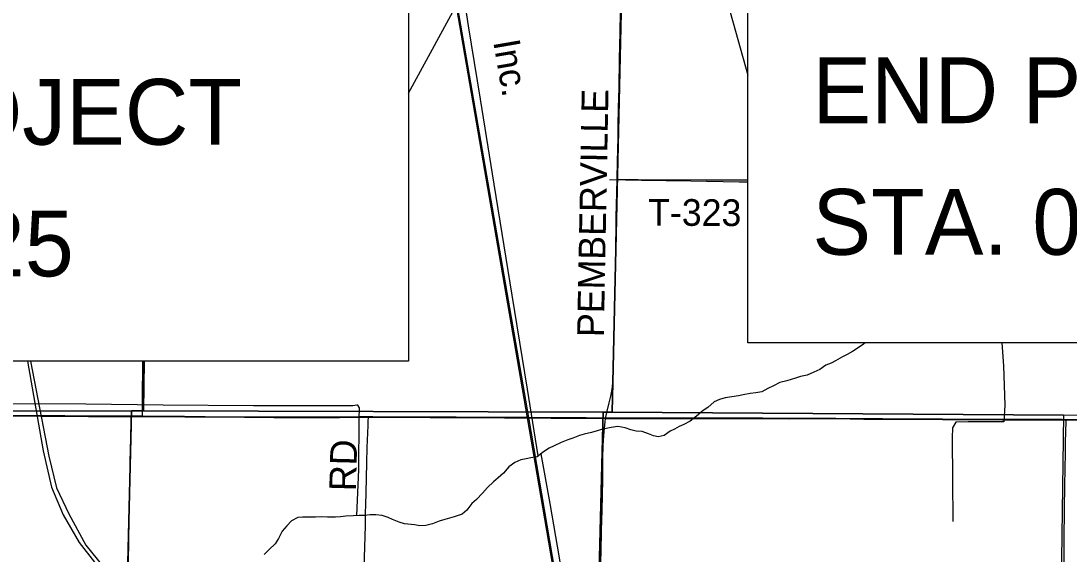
# Model space of a CAD drawing. Extents: x 0 to 34, y 0 to 22.
# Drawn here: x 4.218 to 6.448, y 15.733 to 16.867 of the extents above; entities that cross this region are included whole.
import ezdxf

# ---------------------------------------------------------------- set-up
doc = ezdxf.new("R2010")
doc.units = 0
for name, color, linetype in [('GM_X_County_Road', 7, 'Continuous'), ('GM_X_County_Road_Text', 7, 'Continuous'), ('GM_X_Minor_River', 7, 'Continuous'), ('GM_X_Rail_Line', 7, 'Continuous'), ('GM_X_Rail_Line_Text', 7, 'Continuous'), ('GM_X_Section', 7, 'Continuous'), ('GM_X_Township_Road', 7, 'Continuous'), ('GM_X_Township_Road_Text', 7, 'Continuous'), ('GM_X_US_Route', 7, 'Continuous'), ('SH_Text', 7, 'Continuous'), ('TX_P_1', 7, 'Continuous')]:
    doc.layers.add(name, color=color, linetype=linetype)

msp = doc.modelspace()

# ---------------------------------------------------------------- linework, layer by layer
at = {"layer": 'GM_X_County_Road'}
for p, q in [((4.4524, 16.0253), (4.4762, 16.0252)), ((6.4425, 16.0181), (6.4745, 16.0177))]:
    msp.add_line(p, q, dxfattribs=at)
for points in [[(5.4866, 16.5301), (5.4875, 16.5679), (5.4888, 16.6189), (5.4891, 16.6437), (5.4897, 16.6823), (5.4908, 16.7239), (5.492, 16.7867), (5.4931, 16.8433), (5.4937, 16.8855), (5.4939, 16.9067), (5.4945, 16.9576), (5.4946, 17.0204), (5.4947, 17.038)], [(5.4622, 16.0215), (5.4649, 16.0343), (5.4698, 16.0544), (5.4731, 16.0684), (5.4753, 16.0794), (5.4767, 16.0886), (5.4777, 16.0979), (5.4784, 16.1091), (5.4789, 16.1284), (5.4799, 16.1794), (5.4805, 16.2136), (5.4836, 16.3665), (5.4849, 16.4498), (5.486, 16.5014), (5.4866, 16.5301)], [(3.4764, 16.0302), (3.4941, 16.0299), (3.5158, 16.0296), (3.5842, 16.029), (3.6402, 16.0284), (3.7179, 16.028), (3.7552, 16.0278), (3.8018, 16.0277), (3.8671, 16.0272), (3.9075, 16.0272), (4.0038, 16.0267), (4.0287, 16.0268), (4.0753, 16.0265), (4.1406, 16.0266), (4.2618, 16.0262), (4.3115, 16.026), (4.3613, 16.0257), (4.4141, 16.0255), (4.4524, 16.0253)], [(4.4762, 16.0252), (4.4856, 16.0252), (4.5664, 16.0247), (4.6099, 16.0244), (4.6938, 16.0237), (4.756, 16.0236), (4.7995, 16.0235), (4.8959, 16.0236), (4.9363, 16.0239), (4.9572, 16.0239)], [(4.9572, 16.0239), (4.9674, 16.0239), (5.014, 16.0238), (5.0886, 16.0235), (5.1072, 16.0233), (5.1445, 16.0233), (5.2067, 16.023), (5.2471, 16.0227), (5.2689, 16.0226), (5.2906, 16.0226), (5.2999, 16.0225), (5.3279, 16.0223), (5.3465, 16.0222), (5.4211, 16.0218), (5.4622, 16.0215)], [(5.4507, 15.657), (5.4529, 15.7422), (5.4537, 15.7782), (5.4537, 15.7827), (5.4547, 15.8263), (5.4553, 15.8577), (5.4561, 15.8919), (5.4566, 15.937), (5.4572, 15.9634), (5.4586, 15.9849), (5.4597, 16.0004), (5.461, 16.0139), (5.4622, 16.0215)], [(5.4622, 16.0215), (5.4646, 16.0215), (5.4957, 16.0214), (5.5454, 16.0211), (5.6231, 16.0211), (5.6635, 16.0212), (5.7039, 16.0214), (5.7972, 16.0212), (5.8531, 16.0207), (5.8966, 16.0209), (5.9526, 16.0209), (6.0116, 16.02), (6.0521, 16.0199), (6.1795, 16.0194), (6.3069, 16.0183), (6.3473, 16.0183), (6.4343, 16.0182), (6.4425, 16.0181)]]:
    msp.add_lwpolyline(points, dxfattribs=at)
at = {"layer": 'GM_X_Minor_River'}
for points in [[(5.3189, 15.9417), (5.2959, 16.0838), (5.2634, 16.2838), (5.2253, 16.5197), (5.1957, 16.7006), (5.1705, 16.8565), (5.1572, 16.9463), (5.1426, 17.0309), (5.1183, 17.1951)], [(5.7647, 16.5241), (5.7462, 16.5241), (5.6436, 16.5262), (5.5387, 16.5272), (5.4706, 16.5289)], [(6.0148, 16.1819), (6.0107, 16.1796), (5.9998, 16.1715), (5.9875, 16.1638), (5.976, 16.1573), (5.966, 16.1522), (5.9514, 16.1438), (5.9419, 16.1391), (5.9308, 16.1345), (5.918, 16.1257), (5.905, 16.1195), (5.8909, 16.1134), (5.8768, 16.1107), (5.8661, 16.1068), (5.8478, 16.1016), (5.8329, 16.0977), (5.8195, 16.0905), (5.8076, 16.0851), (5.7946, 16.0782), (5.782, 16.0758), (5.7695, 16.0742), (5.7546, 16.0716), (5.7447, 16.0695), (5.731, 16.0676), (5.7166, 16.0653), (5.7044, 16.0614), (5.6929, 16.0564), (5.6794, 16.0449), (5.6697, 16.0383), (5.6558, 16.0261), (5.6423, 16.0155), (5.6288, 16.0086), (5.6185, 16.0039), (5.6089, 15.9988), (5.5993, 15.9941), (5.587, 15.9853), (5.574, 15.9822), (5.5639, 15.9843), (5.5534, 15.9888), (5.5399, 15.9933), (5.5274, 15.994), (5.5161, 15.9973), (5.5037, 16.0014), (5.4882, 16.004), (5.4738, 16.0021), (5.4635, 16.0001), (5.4536, 15.998), (5.4441, 15.9948)], [(6.3057, 16.1819), (6.3087, 16.1333), (6.3115, 16.0493), (6.3099, 16.0141), (6.2341, 16.014), (6.2072, 16.0135), (6.2005, 16.0012), (6.2, 15.9803), (6.2004, 15.8911), (6.2009, 15.8019)], [(4.9325, 15.8145), (4.9369, 15.913), (4.9376, 16.0208), (4.9386, 16.0439), (4.9346, 16.0493), (4.9327, 16.0494), (4.9239, 16.0484), (4.713, 16.0482), (4.5203, 16.0499), (4.356, 16.0519), (4.1897, 16.0525), (4.0765, 16.0504), (3.9632, 16.0504), (3.8496, 16.0498), (3.7334, 16.0503), (3.5781, 16.0499)], [(5.4441, 15.9948), (5.4323, 15.9913), (5.4166, 15.9875), (5.4063, 15.9847), (5.3922, 15.9794), (5.3819, 15.9759), (5.3673, 15.9701), (5.3524, 15.9633), (5.3424, 15.9582), (5.3298, 15.9506), (5.3166, 15.9399), (5.3029, 15.9375), (5.293, 15.9355), (5.2816, 15.9331), (5.2693, 15.9274), (5.2562, 15.9182), (5.2446, 15.9052), (5.2333, 15.8948), (5.2233, 15.8867), (5.2108, 15.8745), (5.1999, 15.8626), (5.1875, 15.8489), (5.1778, 15.84), (5.1669, 15.8262), (5.1568, 15.8177), (5.1396, 15.8117), (5.1202, 15.8061), (5.108, 15.8026), (5.0934, 15.7969), (5.0797, 15.7934), (5.0668, 15.7926), (5.0555, 15.7948), (5.0343, 15.7968), (5.0231, 15.8009), (5.0088, 15.8062), (4.9991, 15.8106), (4.9863, 15.8147), (4.9731, 15.8165), (4.9614, 15.8164), (4.9492, 15.8148), (4.9375, 15.8147), (4.925, 15.8143), (4.909, 15.8131), (4.8976, 15.8119), (4.8874, 15.8114), (4.87, 15.811), (4.8575, 15.8117), (4.845, 15.8116), (4.8317, 15.8116), (4.8173, 15.8116), (4.8071, 15.8107), (4.794, 15.8038), (4.7835, 15.7926), (4.7738, 15.7815), (4.7662, 15.7657), (4.7591, 15.7545), (4.7463, 15.7423), (4.7354, 15.7316)], [(5.3241, 15.946), (5.3437, 15.8402), (5.3635, 15.7247), (5.3849, 15.5925)]]:
    msp.add_lwpolyline(points, dxfattribs=at)
at = {"layer": 'GM_X_Rail_Line'}
for points in [[(5.5292, 14.4768), (5.5206, 14.546), (5.4959, 14.7503), (5.4725, 14.9371), (5.462, 15.0205), (5.4461, 15.156), (5.4028, 15.3982), (5.2961, 16.0228), (5.1204, 17.0387), (4.9909, 17.7947), (4.7368, 19.2661), (4.6073, 20.0278), (4.4575, 20.9)], [(5.5755, 14.1), (5.542, 14.3915), (5.5241, 14.5438), (5.4984, 14.7506), (5.475, 14.9374), (5.4645, 15.0208), (5.4485, 15.1564), (5.4052, 15.3987), (5.2986, 16.0233), (5.1228, 17.0391), (4.9933, 17.7951), (4.7392, 19.2665), (4.6097, 20.0282), (4.4576, 20.9)], [(4.2319, 16.1435), (4.2654, 15.9524), (4.2832, 15.8753), (4.3076, 15.816), (4.3421, 15.7575), (4.467, 15.5965), (4.6728, 15.341), (4.7136, 15.2817), (4.7513, 15.2282), (4.7901, 15.1572), (4.824, 15.0894), (4.8579, 14.9796), (4.8789, 14.8794), (4.8951, 14.7809), (4.9067, 14.6373)], [(4.2385, 16.1435), (4.2773, 15.9412), (4.2937, 15.874), (4.3201, 15.8186), (4.3563, 15.7514), (4.4159, 15.6771), (4.6754, 15.3582), (4.7729, 15.2528), (5.0077, 15.0761), (5.1902, 14.9484), (5.254, 14.8846)]]:
    msp.add_lwpolyline(points, dxfattribs=at)
at = {"layer": 'GM_X_Section'}
for points in [[(4.4929, 16.8935), (4.4954, 17.0428), (5.4985, 17.0434), (5.476, 16.0344), (5.457, 16.0346), (4.4786, 16.0375), (4.4803, 16.1435)], [(6.4705, 16.1819), (6.4673, 16.0279), (6.437, 16.0283), (5.476, 16.0344), (5.4985, 17.0434), (6.488, 17.04), (6.4858, 16.9319)], [(4.4803, 16.1435), (4.4786, 16.0375), (4.4532, 16.0374), (3.4754, 16.0365), (3.4773, 16.1435)]]:
    msp.add_lwpolyline(points, dxfattribs=at)
for points in [[(3.4754, 16.0365), (4.4532, 16.0374), (4.4299, 15.0671), (3.4378, 15.0391), (3.4686, 16.0366)], [(4.4786, 16.0375), (5.457, 16.0346), (5.4321, 15.051), (4.9949, 15.0647), (4.4299, 15.0671), (4.4532, 16.0374)], [(5.476, 16.0344), (6.437, 16.0283), (6.4232, 15.0563), (5.4321, 15.051), (5.457, 16.0346)]]:
    msp.add_lwpolyline(points, close=True, dxfattribs=at)
at = {"layer": 'GM_X_Township_Road'}
for p, q in [((4.4524, 16.0253), (4.4762, 16.0252)), ((6.4425, 16.0181), (6.4745, 16.0177))]:
    msp.add_line(p, q, dxfattribs=at)
for points in [[(5.4866, 16.5301), (5.4921, 16.53), (5.5313, 16.5299), (5.6767, 16.529), (5.7128, 16.5289), (5.7395, 16.529), (5.7647, 16.5287)], [(4.4762, 16.0252), (4.4762, 16.033), (4.4763, 16.0609), (4.4774, 16.1435)], [(4.432, 15.0602), (4.4321, 15.066), (4.4329, 15.1008), (4.4342, 15.1468), (4.4353, 15.2002), (4.436, 15.2344), (4.437, 15.2817), (4.4376, 15.3277), (4.4383, 15.3581), (4.439, 15.3836), (4.4402, 15.4408), (4.441, 15.4762), (4.4431, 15.575), (4.4438, 15.6043), (4.445, 15.6397), (4.4463, 15.6993), (4.4473, 15.7515), (4.4483, 15.8174), (4.45, 15.8989), (4.4506, 15.9281), (4.4518, 15.9803), (4.4523, 16.0151), (4.4524, 16.0253)], [(4.9374, 15.1861), (4.9376, 15.1996), (4.9381, 15.226), (4.9389, 15.2509), (4.9403, 15.3115), (4.9414, 15.3628), (4.9422, 15.397), (4.9435, 15.4561), (4.9442, 15.4856), (4.9448, 15.5245), (4.9464, 15.5975), (4.9475, 15.6504), (4.9484, 15.6908), (4.9493, 15.725), (4.951, 15.7934), (4.9515, 15.8198), (4.952, 15.8385), (4.9529, 15.8633), (4.9542, 15.927), (4.955, 15.9597), (4.9565, 16.0063), (4.9568, 16.0156), (4.9572, 16.0239)], [(6.4354, 15.441), (6.4358, 15.4549), (6.4358, 15.4766), (6.4358, 15.5093), (6.4361, 15.5637), (6.4367, 15.6196), (6.4373, 15.6725), (6.4382, 15.7595), (6.439, 15.8325), (6.4401, 15.918), (6.4406, 15.9444), (6.441, 15.9693), (6.4415, 15.9942), (6.4423, 16.0128), (6.4425, 16.0181)]]:
    msp.add_lwpolyline(points, dxfattribs=at)
at = {"layer": 'GM_X_US_Route'}
for points in [[(6.4743, 16.0183), (6.4423, 16.0187), (6.4341, 16.0188), (6.3471, 16.0189), (6.3067, 16.0189), (6.1793, 16.02), (6.0518, 16.0205), (6.0114, 16.0206), (5.9524, 16.0215), (5.8964, 16.0214), (5.8529, 16.0213), (5.797, 16.0218), (5.7037, 16.022), (5.6633, 16.0218), (5.6229, 16.0217), (5.5452, 16.0216), (5.4955, 16.0219), (5.4644, 16.022), (5.462, 16.022), (5.4209, 16.0224), (5.3463, 16.0227), (5.3276, 16.0228), (5.2997, 16.0231), (5.2904, 16.0231), (5.2686, 16.0231), (5.2469, 16.0232), (5.2065, 16.0236), (5.1443, 16.0238), (5.107, 16.0239), (5.0884, 16.024), (5.0138, 16.0243), (4.9671, 16.0245), (4.9569, 16.0245), (4.9361, 16.0244), (4.8957, 16.0241), (4.7993, 16.0241), (4.7558, 16.0242), (4.6936, 16.0243), (4.6097, 16.0249), (4.5662, 16.0253), (4.4854, 16.0257), (4.4759, 16.0258), (4.4522, 16.0259), (4.4139, 16.0261), (4.361, 16.0263), (4.3113, 16.0266), (4.2616, 16.0268), (4.1404, 16.0272)], [(4.1404, 16.0272), (4.2616, 16.0268), (4.3113, 16.0266), (4.361, 16.0263), (4.4139, 16.0261), (4.4522, 16.0259), (4.4759, 16.0258), (4.4854, 16.0257), (4.5662, 16.0253), (4.6097, 16.0249), (4.6936, 16.0243), (4.7558, 16.0242), (4.7993, 16.0241), (4.8957, 16.0241), (4.9361, 16.0244), (4.9569, 16.0245), (4.9671, 16.0245), (5.0138, 16.0243), (5.0884, 16.024), (5.107, 16.0239), (5.1443, 16.0238), (5.2065, 16.0236), (5.2469, 16.0232), (5.2686, 16.0231), (5.2904, 16.0231), (5.2997, 16.0231), (5.3276, 16.0228), (5.3463, 16.0227), (5.4209, 16.0224), (5.462, 16.022), (5.4644, 16.022), (5.4955, 16.0219), (5.5452, 16.0216), (5.6229, 16.0217), (5.6633, 16.0218), (5.7037, 16.022), (5.797, 16.0218), (5.8529, 16.0213), (5.8964, 16.0214), (5.9524, 16.0215), (6.0114, 16.0206), (6.0518, 16.0205), (6.1793, 16.02), (6.3067, 16.0189), (6.3471, 16.0189), (6.4341, 16.0188), (6.4423, 16.0187), (6.4743, 16.0183)]]:
    msp.add_lwpolyline(points, dxfattribs=at)
at = {"layer": 'SH_Text'}
for points in [[(5.7647, 16.9319), (7.7647, 16.9319), (7.7647, 16.1819), (5.7647, 16.1819)], [(3.0426, 16.8935), (5.0426, 16.8935), (5.0426, 16.1435), (3.0426, 16.1435)]]:
    msp.add_lwpolyline(points, close=True, dxfattribs=at)
at = {"layer": 'TX_P_1'}
for points in [[(5.0426, 16.7134), (5.4967, 17.5463), (5.0426, 16.8935)], [(5.7647, 16.9319), (5.5424, 17.5463), (5.7647, 16.7518)]]:
    msp.add_lwpolyline(points, close=True, dxfattribs=at)

# ---------------------------------------------------------------- texts
at = {"layer": 'GM_X_County_Road_Text'}
msp.add_text('PEMBERVILLE', height=0.056818, rotation=88.9085, dxfattribs=at).set_placement((5.4583, 16.194))
at = {"layer": 'GM_X_Rail_Line_Text'}
msp.add_text('Inc.', height=0.05663, rotation=279.7937, dxfattribs=at).set_placement((5.2228, 16.8229))
at = {"layer": 'GM_X_Township_Road_Text'}
for s, rotation, p in [('T-323', 359.7178, (5.5525, 16.4315)), ('RD', 88.5174, (4.9308, 15.8661))]:
    msp.add_text(s, height=0.05682, rotation=rotation, dxfattribs=at).set_placement(p)
at = {"layer": 'SH_Text'}
for s, p in [('END PROJECT', (5.9023, 16.6495)), ('BEGIN PROJECT', (3.1802, 16.6036)), ('STA. 0+62.00', (5.9023, 16.3695)), ('STA. 0+11.25', (3.1802, 16.3236))]:
    msp.add_text(s, height=0.14, dxfattribs=at).set_placement(p)

doc.saveas('drawing.dxf')
